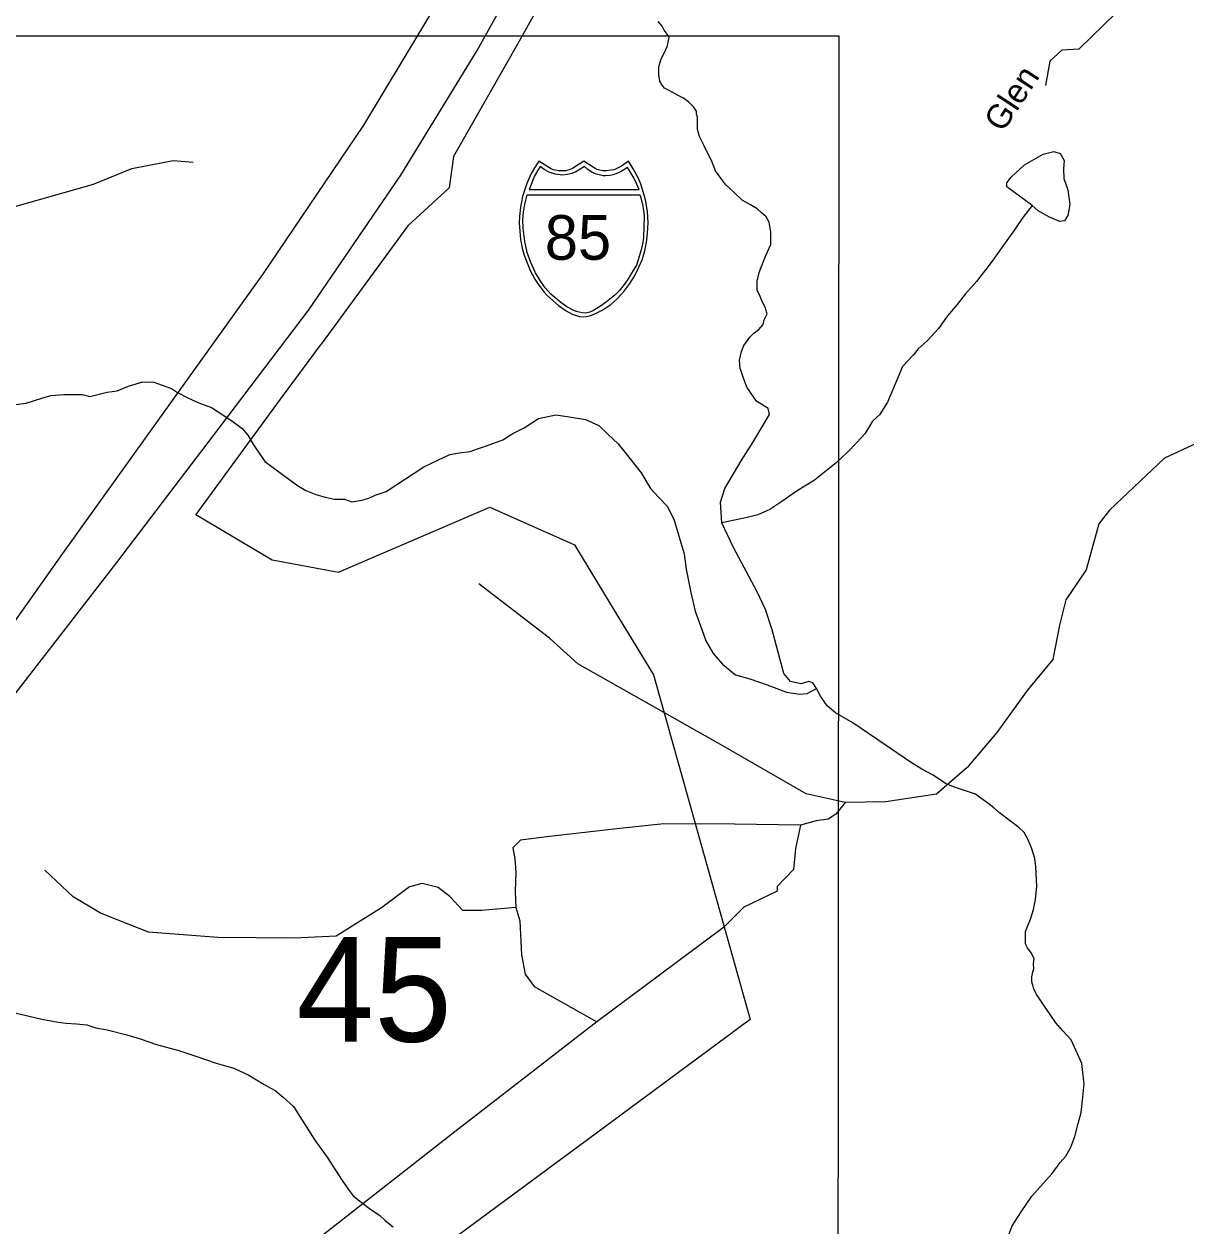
# Model space of a CAD drawing. Extents: x 2056842 to 2160602, y 826753 to 1016856.
# Drawn here: x 2082784 to 2087342, y 872595 to 877308 of the extents above; entities that cross this region are included whole.
import ezdxf

# ---------------------------------------------------------------- set-up
doc = ezdxf.new("R2010")
doc.units = 0
for name, color, linetype in [('Exist Boundary Political City Limit New', 7, 'Continuous'), ('Exist Hydrographic Creek Single Shore', 7, 'Continuous'), ('Exist Hydrographic Misc Water Feature', 7, 'Continuous'), ('Exist Road Non-System Type 51', 7, 'Continuous'), ('Exist Road Non-System Type 51 Label', 7, 'Continuous'), ('Exist Road Primary Interstate Divided Center Attributed', 7, 'Continuous'), ('Exist Road Primary Interstate Shield CELL', 7, 'Continuous'), ('Exist Road Primary Interstate Shield Number Label', 7, 'Continuous'), ('Exist Road Secondary Structure Standard Bridge Number Label', 7, 'Continuous'), ('Map Preparation Boundary City Limit Buffer Line', 7, 'Continuous'), ('Map Preparation Inset Cut Line', 7, 'Continuous')]:
    doc.layers.add(name, color=color, linetype=linetype)

msp = doc.modelspace()

# ---------------------------------------------------------------- linework, layer by layer
at = {"layer": 'Exist Boundary Political City Limit New'}
msp.add_lwpolyline([(2085000, 877731.6), (2084730.8, 877247.3), (2084469.2, 876788.1), (2084452.1, 876665.7), (2084290, 876516.9), (2083949.5, 876053), (2083946, 876048.2), (2083879.5, 875958.8), (2083788.8, 875836.6), (2083458.2, 875385.2), (2083758, 875206.8), (2084017.5, 875158.8), (2084610.8, 875413.8), (2084943.5, 875265.2), (2085000, 875172.5), (2085104.9, 875000), (2085253.5, 874755.8), (2085632.8, 873403.8), (2085000, 872936.6), (2084465, 872541.6)], dxfattribs=at)
at = {"layer": 'Exist Hydrographic Creek Single Shore'}
for points in [[(2085521.5, 875352.7), (2085516.5, 875432.7), (2085532.8, 875486.5), (2085597.7, 875595.2), (2085642.7, 875666.5), (2085707.7, 875776.8), (2085702.7, 875800.5), (2085657.7, 875829.3), (2085619.4, 875883.7), (2085605.5, 875923.6), (2085597.5, 875947.4), (2085593.4, 875957.7), (2085591.1, 875989.6), (2085599, 876023.5), (2085607.1, 876047.6), (2085631, 876079.6), (2085646.8, 876095.7), (2085666.8, 876109.7), (2085682.9, 876129.7), (2085686.9, 876147.7), (2085698.6, 876171.7), (2085696.8, 876180), (2085692.5, 876195.8), (2085680.5, 876217.7), (2085668.6, 876245.9), (2085660.4, 876263.8), (2085660.4, 876279.8), (2085660.2, 876299.8), (2085668.1, 876333.8), (2085684, 876373.8), (2085694.1, 876399.9), (2085713.7, 876443.8), (2085713.8, 876463.8), (2085713.7, 876492), (2085709.6, 876515.7), (2085707.6, 876531.8), (2085695.6, 876551.8), (2085675.3, 876569.6), (2085659.5, 876583.7), (2085633.2, 876599.6), (2085601.1, 876617.4), (2085569.3, 876647.2), (2085537.1, 876677.4), (2085516.9, 876703.1), (2085496.9, 876733.1), (2085480.7, 876773.1), (2085462.7, 876808.9), (2085450.7, 876833.1), (2085438.4, 876857), (2085434.4, 876866.9), (2085426.4, 876895), (2085426.2, 876918.9), (2085426.4, 876942.9), (2085422.4, 876954.8), (2085422.3, 876966.9), (2085410.2, 876982.9), (2085402.1, 876990.9), (2085390.2, 877002.7), (2085367.9, 877018.9), (2085348.1, 877028.8), (2085312.1, 877048.6), (2085295.9, 877056.5), (2085287.9, 877068.4), (2085277.8, 877084.4), (2085273.7, 877108.4), (2085273.7, 877140.3), (2085281.5, 877168.3), (2085301.3, 877208.6), (2085307.5, 877220.6), (2085307.6, 877224.5), (2085311.4, 877236.6), (2085315.4, 877256.5), (2085307.2, 877268.5), (2085295.3, 877284.5), (2085287.1, 877300.4), (2085271.1, 877318.5)], [(2082752.6, 875816.7), (2082792.3, 875820.9), (2082854.3, 875841.1), (2082889.9, 875851.1), (2082940.4, 875855.3), (2083012.2, 875855.7), (2083042.3, 875847.5), (2083110.2, 875864), (2083150.2, 875870), (2083194, 875888.2), (2083250.2, 875904.4), (2083293.9, 875904.3), (2083326.1, 875892.5), (2083362.4, 875878.5), (2083386.2, 875862.7), (2083426.2, 875842.9), (2083470.4, 875823.2), (2083520.1, 875805), (2083564.4, 875775.2), (2083608.2, 875745.5), (2083640.4, 875721.5), (2083662.6, 875695.8), (2083687, 875653.6), (2083729, 875592), (2083857, 875498.4), (2083889.4, 875478.4), (2083929.1, 875462.7), (2083965.4, 875452.7), (2084001.5, 875444.8), (2084041.5, 875444.9), (2084069.6, 875434.9), (2084109.2, 875441.1), (2084137.3, 875449), (2084161.5, 875461.2), (2084205.1, 875475.6), (2084352.8, 875571.7), (2084406.9, 875598), (2084454.7, 875620), (2084490.6, 875626.3), (2084534.5, 875632.2), (2084562.6, 875642.5), (2084598.6, 875654.5), (2084662.2, 875677), (2084702.2, 875702.9), (2084746.3, 875725.1), (2084802.1, 875761.2), (2084870.3, 875775.3), (2084914.4, 875769.3), (2084986.4, 875757.7), (2085038.5, 875734), (2085074.6, 875700), (2085114.6, 875662.3), (2085146.5, 875622.2), (2085204.8, 875548.4), (2085241.1, 875486.5), (2085273.1, 875452.9), (2085307.3, 875416.9), (2085333.6, 875367), (2085373.7, 875231.1), (2085381.9, 875171), (2085400.2, 875079.3), (2085416.4, 875005.1), (2085442.6, 874933.4), (2085458.8, 874889.5), (2085486.9, 874839.3), (2085523.4, 874797.7), (2085575.5, 874755.8), (2085631.5, 874740), (2085699.4, 874716.3), (2085775.4, 874688.5), (2085827.7, 874680.6), (2085855.6, 874682.5), (2085892.6, 874702.2)], [(2085892.6, 874702.2), (2085878.9, 874724.7), (2085862.6, 874729.7), (2085831.4, 874721), (2085790.1, 874729.7), (2085765.2, 874761), (2085718.5, 874932), (2085692.3, 875012), (2085659.9, 875081.9), (2085566.5, 875255.2), (2085521.5, 875352.7)], [(2086648, 872563.2), (2086659.8, 872595.1), (2086695.7, 872649.5), (2086737.4, 872711.6), (2086781.4, 872761.6), (2086816.9, 872799.9), (2086849, 872843.9), (2086870.9, 872868), (2086890.6, 872904), (2086906.6, 872946), (2086918.5, 872996), (2086930.2, 873040), (2086938, 873100.2), (2086942, 873152), (2086937.7, 873196.1), (2086933.8, 873231.9), (2086911.6, 873281.9), (2086891.4, 873324), (2086859.4, 873359.8), (2086831.2, 873391.9), (2086772.9, 873477.4), (2086757, 873501.3), (2086745, 873523.6), (2086740.7, 873539.4), (2086736.7, 873551.3), (2086736.8, 873571.3), (2086740.8, 873591.6), (2086744.6, 873603.3), (2086744.4, 873623.3), (2086746.4, 873643.3), (2086734.4, 873665.5), (2086720.4, 873685.5), (2086712.2, 873701.4), (2086712.4, 873709.3), (2086712.1, 873725.4), (2086712.2, 873749.3), (2086720.2, 873769.2), (2086731.9, 873797.5), (2086743.9, 873835.3), (2086751.6, 873875.5), (2086757.5, 873925.6), (2086753.2, 874003.4), (2086749.3, 874035.3), (2086737, 874073.3), (2086722.9, 874109.4), (2086706.8, 874137.3), (2086686.8, 874157), (2086610.6, 874215.1), (2086588.7, 874234.9), (2086564.5, 874252.8), (2086536.7, 874272.7), (2086516.3, 874288.5), (2086476.5, 874300.5), (2086430.3, 874316.2), (2086398.4, 874330.3), (2086350.2, 874362.2), (2086306.1, 874386.1), (2086262, 874413.9), (2086130, 874503.6), (2086035.5, 874567.2), (2085967.4, 874607), (2085935.1, 874634.7), (2085908.8, 874672.2), (2085892.6, 874702.2)], [(2082738, 873433), (2082854.1, 873405.3), (2082917.8, 873393.5), (2082950, 873389.5), (2082990, 873387.9), (2083030.2, 873383.9), (2083066.1, 873371.9), (2083110.2, 873364), (2083188.1, 873344.5), (2083240.2, 873328.4), (2083304.2, 873306.6), (2083391.9, 873283.1), (2083454.2, 873261.2), (2083538.3, 873233.4), (2083606.6, 873213.7), (2083666.5, 873185.9), (2083726.4, 873150), (2083768.8, 873126.2), (2083801, 873100.2), (2083841, 873062.5), (2083925.3, 872930.8), (2083975.7, 872861.1), (2084003.6, 872817.1), (2084031.7, 872773), (2084055.7, 872739.4), (2084075.6, 872713.3), (2084100, 872693.4), (2084139.9, 872663.3), (2084179.9, 872635.7), (2084200.4, 872615.6), (2084232.2, 872591.8)]]:
    msp.add_lwpolyline(points, dxfattribs=at)
at = {"layer": 'Exist Hydrographic Misc Water Feature'}
for points in [[(2086739.2, 876597.2), (2086639.8, 876669.4), (2086639.8, 876685.6), (2086656, 876708.1), (2086708.5, 876755.7), (2086782.2, 876798.2), (2086823.5, 876808.2), (2086848.5, 876800.7), (2086864.7, 876773.2), (2086861, 876740.6), (2086863.5, 876701.9), (2086878.4, 876658.1), (2086885.9, 876600.6), (2086878.4, 876556.9), (2086866, 876536.9), (2086847.2, 876534.4), (2086807.2, 876550.6), (2086762.2, 876575.6), (2086739.2, 876597.2)], [(2086739.2, 876597.2), (2086701.5, 876549.1), (2086669.7, 876501.1), (2086625.6, 876440.8), (2086582.1, 876378.9), (2086520.4, 876298.5), (2086476.3, 876248.4), (2086444.5, 876208.2), (2086406.6, 876164.4), (2086371.1, 876114.2), (2086327, 876066.2), (2086290.9, 876033.9), (2086271.3, 876010.1), (2086229.4, 875965.7), (2086199.7, 875893.5), (2086171.8, 875825.5), (2086140, 875775.5), (2086112.1, 875751.3), (2086082.2, 875701.1), (2086050.6, 875666.9), (2086014.5, 875629), (2085970.4, 875587), (2085884.7, 875518.8), (2085812.8, 875474.5), (2085760.9, 875438.2), (2085709.4, 875404.2), (2085662.7, 875383.9), (2085620.2, 875372.7), (2085521.5, 875352.7)]]:
    msp.add_lwpolyline(points, dxfattribs=at)
at = {"layer": 'Exist Road Non-System Type 51'}
for points in [[(2088159.7, 878471.4), (2088180.6, 878338.3), (2088178.7, 878311.7), (2088114.1, 878267.9), (2088005.8, 878239.4), (2087969.9, 878233), (2087940.2, 878215.6), (2087922.2, 878174.8), (2087900.3, 878111.1), (2087855.7, 878055.9), (2087730.3, 877973.2), (2087312.2, 877591), (2086921.7, 877209.7), (2086855.2, 877205.9), (2086807.7, 877162.2), (2086790.6, 877067.1)], [(2080758.8, 876324.3), (2081076.4, 876374.4), (2081404.1, 876435.5), (2081507.6, 876458.6), (2081625.3, 876443.7), (2081723.6, 876437.8), (2081817.5, 876403.5), (2081903.9, 876406.5), (2082121.3, 876346.8), (2082344, 876353.5), (2082423, 876371.4), (2082490, 876413.2), (2082625.6, 876539.9), (2082720.2, 876585.3), (2083056.8, 876680.7), (2083207.3, 876741.8), (2083369.6, 876773.1), (2083447.8, 876766.4)], [(2087663.8, 875856.8), (2087538.3, 875773.2), (2087382.5, 875662.9), (2087257.1, 875605.8), (2087042.4, 875402.4), (2086999.6, 875348.2), (2086950.2, 875167.5), (2086870.4, 875049.6), (2086845.7, 874950.8), (2086819.1, 874815.8), (2086719.4, 874695), (2086599.6, 874529.6), (2086483.7, 874392.7), (2086364, 874288.1), (2086164.5, 874257.7), (2086004.9, 874255.8)], [(2086004.9, 874255.8), (2085851.9, 874289), (2085515.6, 874483), (2084955.9, 874799.6), (2084845.7, 874900.4), (2084568.3, 875113.3)], [(2086004.9, 874255.8), (2085968.3, 874209.6), (2085938.8, 874189.7), (2085891.3, 874183), (2085829.6, 874166.9)], [(2085829.6, 874166.9), (2085571.1, 874169.7), (2085293.7, 874171.6), (2085109.4, 874152.6), (2084834.8, 874121.2), (2084732.2, 874107.9), (2084701.8, 874077.5), (2084709.4, 874033.8), (2084713.2, 873982.4), (2084711.3, 873906.4), (2084713.2, 873843.6)], [(2085829.6, 874166.9), (2085810.6, 874074.6), (2085803, 873992.9), (2085738.4, 873926.3), (2085738.4, 873907.3), (2085607.2, 873844.6), (2085528.4, 873765.6), (2085030.5, 873395.8)], [(2084713.2, 873843.6), (2084579.2, 873831.2), (2084505.1, 873831.2), (2084453.8, 873886.4), (2084408.2, 873922.5), (2084345.5, 873937.7), (2084296.1, 873924.4), (2084185.9, 873842.7), (2084009.2, 873730.5), (2083843.8, 873722.9), (2083544.6, 873725.7), (2083272.8, 873746.6), (2083084.7, 873820.8), (2082976.4, 873885.4), (2082866.2, 873990)], [(2084713.2, 873843.6), (2084728.9, 873790.8), (2084735.5, 873657.7), (2084749.8, 873581.7), (2084784.9, 873533.2), (2085030.5, 873395.8)], [(2085030.5, 873395.8), (2084451, 872946.1), (2083570.2, 872256.8), (2083490.4, 872201.7), (2083433.4, 872190.3)]]:
    msp.add_lwpolyline(points, dxfattribs=at)
at = {"layer": 'Exist Road Primary Interstate Divided Center Attributed'}
for points in [[(2086913.8, 881656.6), (2086812.4, 881495.1), (2086697.2, 881298.8), (2086416.5, 880823.6), (2086104.3, 880294.3), (2085757.9, 879705.6), (2085389, 879075.5), (2085071.4, 878540.8), (2084756.5, 877997.1), (2084428.1, 877431.8), (2084115.8, 876911.6), (2083719, 876326.5), (2083315.1, 875763), (2082934.5, 875231.9), (2082589.9, 874745.8), (2082168.8, 874149.9), (2082016.5, 873938.4)], [(2082028.6, 873734.2), (2082362.2, 874180.5), (2082750, 874681), (2083148.6, 875195.9), (2083527.4, 875694.6), (2083900.8, 876187.9), (2084261.6, 876715.3), (2084561.2, 877205), (2084920.2, 877849.5), (2085220.7, 878395), (2085715.6, 879311.3), (2085981, 879788.4), (2086215.9, 880224.1), (2086495.7, 880739), (2086767.4, 881239.4), (2086966.9, 881577.7)]]:
    msp.add_lwpolyline(points, dxfattribs=at)
at = {"layer": 'Exist Road Primary Interstate Shield CELL'}
for points in [[(2084979.8, 876160), (2084989.3, 876160.9), (2085002, 876163.4), (2085014.4, 876167.5), (2085028.5, 876173.7), (2085049.3, 876185.2), (2085066.1, 876195.1), (2085085.4, 876208.1), (2085111.6, 876231.8), (2085137.6, 876259.2), (2085160.6, 876290.2), (2085178.9, 876319.2), (2085194.9, 876352.4), (2085208.4, 876383.3), (2085219, 876418.6), (2085226.1, 876452.9), (2085229.7, 876488.6), (2085232, 876528.1), (2085229.3, 876572.7), (2085221.6, 876618.2), (2085214.3, 876646.6), (2085203.3, 876680.5), (2085194.3, 876702.2), (2085173.5, 876740.6), (2085154.7, 876770.2), (2085127.5, 876751.1), (2085109.7, 876741.6), (2085098.9, 876736.8), (2085087.7, 876734.6), (2085067.2, 876732.1), (2085054.4, 876732.7), (2085042.4, 876735.4), (2085032.3, 876737.6), (2085024, 876741.6), (2084979.8, 876770.2), (2084935.5, 876741.6), (2084926.2, 876737.4), (2084916.7, 876735.4), (2084907.6, 876732.8), (2084892.5, 876732.1), (2084880.9, 876732.5), (2084869, 876734.6), (2084859.6, 876736.6), (2084849.1, 876741.6), (2084804, 876770.2), (2084786.3, 876744.5), (2084771.8, 876719.1), (2084756.5, 876683.2), (2084746.9, 876655.4), (2084740.1, 876632.5), (2084731.8, 876590.5), (2084727.4, 876554), (2084726.7, 876528.1), (2084731.4, 876463.6), (2084738.5, 876429.3), (2084745.7, 876401.5), (2084769.6, 876341.4), (2084787.5, 876307.8), (2084802.9, 876283.7), (2084824.5, 876256.5), (2084836.2, 876243.5), (2084881, 876204.4), (2084910.9, 876183.9), (2084934.8, 876171), (2084946.1, 876166.7), (2084963.6, 876161.8)], [(2084809.4, 876749.5), (2084798.4, 876732.6), (2084785.7, 876709.7), (2084775.6, 876686.1), (2084765.2, 876659.9), (2085196.8, 876659.8), (2085186.7, 876682.2), (2085176, 876704.7), (2085164.7, 876725.3), (2085151, 876745.2), (2085126.8, 876729.9), (2085109.2, 876721.6), (2085095, 876716.7), (2085083, 876714), (2085064.4, 876712.5), (2085056.1, 876713), (2085030.2, 876718.9), (2085012.6, 876726.1), (2084995.9, 876737.2), (2084982.4, 876749.9), (2084948.2, 876729.2), (2084933, 876722.6), (2084915.6, 876718.1), (2084896.5, 876715.7), (2084867.1, 876718.9), (2084844, 876726.9), (2084824.1, 876737.2)], [(2085199.3, 876638.4), (2085203.9, 876626.3), (2085210.3, 876599.2), (2085213.6, 876578.4), (2085217.1, 876554.4), (2085215.9, 876513.3), (2085213.9, 876470.7), (2085210, 876445.5), (2085204.7, 876422.5), (2085197.6, 876397.1), (2085186.1, 876363.2), (2085170.1, 876334.6), (2085150.3, 876302.8), (2085128.8, 876274.9), (2085119.5, 876263.3), (2085101.7, 876244.7), (2085069.5, 876218.8), (2085046, 876201.2), (2085017.8, 876184.6), (2085003.5, 876178.2), (2084986.9, 876174.7), (2084973.2, 876175.7), (2084956.5, 876180.1), (2084943.1, 876183.8), (2084913.6, 876199.7), (2084889.8, 876215.6), (2084850, 876248.2), (2084828.6, 876273.4), (2084808.5, 876302.7), (2084790.7, 876332.8), (2084771.6, 876372.5), (2084758.1, 876412.4), (2084748.3, 876455.5), (2084741.7, 876508.1), (2084741, 876540.2), (2084743, 876571), (2084745.9, 876587.2), (2084749.8, 876607.3), (2084757.7, 876638.2)]]:
    msp.add_lwpolyline(points, close=True, dxfattribs=at)
at = {"layer": 'Map Preparation Boundary City Limit Buffer Line'}
msp.add_lwpolyline([(2085000, 877731.6), (2084730.8, 877247.3), (2084469.2, 876788.1), (2084452.1, 876665.7), (2084290, 876516.9), (2083949.5, 876053), (2083946, 876048.2), (2083879.5, 875958.8), (2083788.8, 875836.6), (2083458.2, 875385.2), (2083758, 875206.8), (2084017.5, 875158.8), (2084610.8, 875413.8), (2084943.5, 875265.2), (2085000, 875172.5), (2085104.9, 875000), (2085253.5, 874755.8), (2085632.8, 873403.8), (2085000, 872936.6), (2084465, 872541.6)], dxfattribs=at)
at = {"layer": 'Map Preparation Inset Cut Line'}
msp.add_lwpolyline([(2059276.8, 845851.8), (2104036.2, 845851.8), (2104036.2, 868310.8), (2085975.1, 868308.6), (2085982, 877260.1), (2059276.8, 877260.1), (2059276.8, 845851.8)], dxfattribs=at)

# ---------------------------------------------------------------- texts
at = {"layer": 'Exist Road Non-System Type 51 Label'}
msp.add_text('Glen', height=95, rotation=56.5538, dxfattribs=at).set_placement((2086623.1, 876879.6))
at = {"layer": 'Exist Road Primary Interstate Shield Number Label'}
msp.add_text('85', height=175, dxfattribs=at).set_placement((2084826.9, 876383.8))
at = {"layer": 'Exist Road Secondary Structure Standard Bridge Number Label'}
msp.add_text('45', height=410.1, dxfattribs=at).set_placement((2083852.8, 873317.4))

doc.saveas('drawing.dxf')
